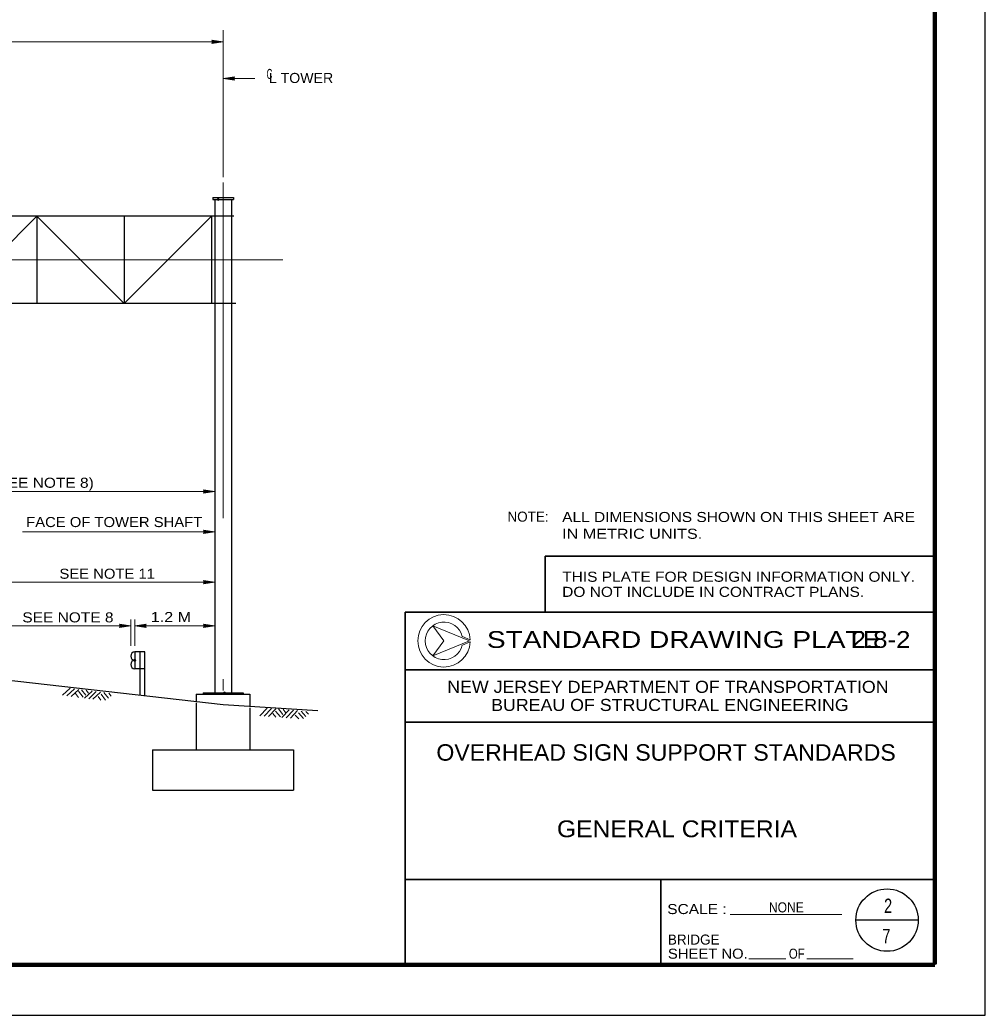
# Model space of a CAD drawing. Extents: x 312601.858 to 312602.699, y 144420.127 to 144420.721.
# Drawn here: x 312602.4113 to 312602.6988, y 144420.1268 to 144420.4233 of the extents above; entities that cross this region are included whole.
import ezdxf
from ezdxf.enums import TextEntityAlignment as Align

# ---------------------------------------------------------------- set-up
doc = ezdxf.new("R2010")
doc.units = 0
doc.header["$LTSCALE"] = 0.0012
doc.header["$PDMODE"] = 32
doc.header["$PDSIZE"] = 0.0006
doc.linetypes.add('DOT_DASHED', pattern=[7.7, 5, -1.2, 0.3, -1.2])
doc.linetypes.add('LONG_DASHED', pattern=[7.5, 6, -1.5])
for name, color, linetype, lineweight in [('1', 7, 'Continuous', 13), ('2', 7, 'Continuous', 13), ('39', 7, 'Continuous', 13)]:
    doc.layers.add(name, color=color, linetype=linetype, lineweight=lineweight)
doc.layers.add('4', color=7, linetype='Continuous')
doc.layers.add('51', color=7, linetype='Continuous')

msp = doc.modelspace()

# ---------------------------------------------------------------- hatches: boundary and pattern name
at = {"layer": '39'}
for points in [[(312602.4687, 144420.4168), (312602.4684, 144420.4173), (312602.4718, 144420.4168), (312602.4684, 144420.4163)], [(312602.4687, 144420.4168), (312602.4684, 144420.4173), (312602.4718, 144420.4168), (312602.4684, 144420.4163)], [(312602.4749, 144420.4058), (312602.4752, 144420.4053), (312602.4718, 144420.4058), (312602.4752, 144420.4063)], [(312602.4662, 144420.2828), (312602.4659, 144420.2833), (312602.4693, 144420.2828), (312602.4659, 144420.2823)], [(312602.4662, 144420.2828), (312602.4659, 144420.2833), (312602.4693, 144420.2828), (312602.4659, 144420.2823)], [(312602.4662, 144420.2708), (312602.4659, 144420.2713), (312602.4693, 144420.2708), (312602.4659, 144420.2703)], [(312602.4662, 144420.2708), (312602.4659, 144420.2713), (312602.4693, 144420.2708), (312602.4659, 144420.2703)], [(312602.4662, 144420.2558), (312602.4659, 144420.2563), (312602.4693, 144420.2558), (312602.4659, 144420.2553)], [(312602.4412, 144420.2428), (312602.4409, 144420.2433), (312602.4443, 144420.2428), (312602.4409, 144420.2423)], [(312602.4486, 144420.2428), (312602.4489, 144420.2423), (312602.4455, 144420.2428), (312602.4489, 144420.2433)], [(312602.4662, 144420.2428), (312602.4659, 144420.2433), (312602.4693, 144420.2428), (312602.4659, 144420.2423)], [(312602.4662, 144420.2428), (312602.4659, 144420.2433), (312602.4693, 144420.2428), (312602.4659, 144420.2423)], [(312602.4662, 144420.2428), (312602.4659, 144420.2433), (312602.4693, 144420.2428), (312602.4659, 144420.2423)]]:
    msp.add_hatch(color=256, dxfattribs=at).paths.add_polyline_path(points)

# ---------------------------------------------------------------- linework, layer by layer
at = {"layer": '1'}
for p, q in [((312602.5431, 144420.237), (312602.5454, 144420.238)), ((312602.4239, 144420.2221), (312602.4262, 144420.2242)), ((312602.4252, 144420.2219), (312602.4275, 144420.224)), ((312602.4265, 144420.2217), (312602.4288, 144420.2238)), ((312602.4278, 144420.2226), (312602.4287, 144420.2214)), ((312602.4287, 144420.2233), (312602.4301, 144420.2215)), ((312602.4296, 144420.2237), (312602.4309, 144420.2221)), ((312602.4305, 144420.2212), (312602.4328, 144420.2233)), ((312602.431, 144420.2236), (312602.4317, 144420.2227)), ((312602.4318, 144420.221), (312602.434, 144420.2232)), ((312602.433, 144420.2209), (312602.4353, 144420.223)), ((312602.4355, 144420.2224), (312602.4368, 144420.2206)), ((312602.4363, 144420.2229), (312602.4376, 144420.2212)), ((312602.4377, 144420.2227), (312602.4384, 144420.2218)), ((312602.4346, 144420.2217), (312602.4354, 144420.2206)), ((312602.4827, 144420.216), (312602.4849, 144420.2182)), ((312602.484, 144420.2159), (312602.4862, 144420.2181)), ((312602.4853, 144420.2158), (312602.4875, 144420.218)), ((312602.4866, 144420.2167), (312602.4875, 144420.2156)), ((312602.4874, 144420.2174), (312602.4889, 144420.2157)), ((312602.4883, 144420.218), (312602.4896, 144420.2164)), ((312602.4893, 144420.2155), (312602.4915, 144420.2177)), ((312602.4897, 144420.2179), (312602.4904, 144420.217)), ((312602.4906, 144420.2154), (312602.4928, 144420.2176)), ((312602.4919, 144420.2153), (312602.494, 144420.2175)), ((312602.4942, 144420.2169), (312602.4957, 144420.2152)), ((312602.495, 144420.2174), (312602.4964, 144420.2158)), ((312602.4964, 144420.2173), (312602.4972, 144420.2165)), ((312602.4933, 144420.2162), (312602.4943, 144420.2151)), ((312602.6284, 144420.1436), (312602.6394, 144420.1436)), ((312602.6457, 144420.1436), (312602.6595, 144420.1436))]:
    msp.add_line(p, q, dxfattribs=at)
for points in [[(312602.5452, 144420.2383), (312602.5343, 144420.2428), (312602.5452, 144420.2383)], [(312602.5454, 144420.2386), (312602.5431, 144420.2396), (312602.543, 144420.2396)]]:
    msp.add_lwpolyline(points, dxfattribs=at)
for points in [[(312602.5452, 144420.2383), (312602.5343, 144420.2428), (312602.5375, 144420.2383), (312602.5343, 144420.2338)], [(312602.5375, 144420.2383), (312602.5343, 144420.2338), (312602.5452, 144420.2383), (312602.5343, 144420.2428)]]:
    msp.add_lwpolyline(points, close=True, dxfattribs=at)
for radius, start, end in [(0.0078026, 2.21392, 357.78608), (0.0056, 13.69411, 346.30589)]:
    msp.add_arc((312602.5376, 144420.2383), radius, start, end, dxfattribs=at)
at = {"layer": '39', "lineweight": 25}
for p, q in [((312602.6988, 144420.1268), (312602.6988, 144420.7208)), ((312602.4687, 144420.3704), (312602.4687, 144420.3698)), ((312602.4687, 144420.3698), (312602.4749, 144420.3698)), ((312602.475, 144420.3648), (312601.9956, 144420.3648)), ((312602.3903, 144420.3388), (312602.4163, 144420.3648)), ((312602.4163, 144420.3648), (312602.4163, 144420.3388)), ((312602.4423, 144420.3388), (312602.4163, 144420.3648)), ((312602.4423, 144420.3648), (312602.4423, 144420.3388)), ((312602.4423, 144420.3388), (312602.4683, 144420.3648)), ((312602.4683, 144420.3648), (312602.4683, 144420.3388)), ((312602.4756, 144420.3388), (312601.9952, 144420.3388)), ((312602.447, 144420.235), (312602.447, 144420.2221)), ((312602.4485, 144420.2219), (312602.4485, 144420.235)), ((312602.4485, 144420.23), (312602.4455, 144420.23)), ((312602.4638, 144420.2224), (312602.4798, 144420.2224)), ((312602.4638, 144420.2224), (312602.4638, 144420.2202)), ((312602.4658, 144420.2228), (312602.4778, 144420.2228)), ((312602.4658, 144420.2228), (312602.4658, 144420.2224)), ((312602.4778, 144420.2228), (312602.4778, 144420.2224)), ((312602.4798, 144420.2224), (312602.4798, 144420.2188)), ((312602.6789, 144420.1551), (312602.6603, 144420.1551)), ((312601.8578, 144420.1268), (312602.6988, 144420.1268))]:
    msp.add_line(p, q, dxfattribs=at)
at = {"layer": '39', "lineweight": 158}
for p, q in [((312602.6838, 144420.142), (312602.6838, 144420.6818)), ((312601.9088, 144420.1418), (312602.6838, 144420.1418))]:
    msp.add_line(p, q, dxfattribs=at)
at = {"layer": '39'}
for p, q in [((312602.4718, 144420.4202), (312602.4718, 144420.3764)), ((312602.4718, 144420.4168), (312601.9448, 144420.4168)), ((312602.4812, 144420.4058), (312602.4718, 144420.4058)), ((312602.3095, 144420.2828), (312602.4693, 144420.2828)), ((312602.412, 144420.2708), (312602.4693, 144420.2708)), ((312602.4443, 144420.2447), (312602.4443, 144420.2368)), ((312602.4455, 144420.2447), (312602.4455, 144420.2368)), ((312602.4063, 144420.2428), (312602.4442, 144420.2428)), ((312602.4455, 144420.2428), (312602.4693, 144420.2428)), ((312602.4718, 144420.2269), (312602.4718, 144420.2235)), ((312602.6022, 144420.1672), (312602.6838, 144420.1672)), ((312602.6229, 144420.1568), (312602.6561, 144420.1568))]:
    msp.add_line(p, q, dxfattribs=at)
at = {"layer": '39', "linetype": 'DOT_DASHED'}
for p, q in [((312602.4718, 144420.3749), (312602.4718, 144420.2269)), ((312602.0009, 144420.3518), (312602.4896, 144420.3518))]:
    msp.add_line(p, q, dxfattribs=at)
at = {"layer": '39', "lineweight": 35}
for p, q in [((312602.5677, 144420.2635), (312602.6838, 144420.2635)), ((312602.5677, 144420.2468), (312602.5677, 144420.2635)), ((312602.526, 144420.1418), (312602.526, 144420.2468)), ((312602.526, 144420.2297), (312602.6838, 144420.2297)), ((312602.526, 144420.2141), (312602.6838, 144420.2141)), ((312602.526, 144420.1672), (312602.6838, 144420.1672)), ((312602.6022, 144420.1421), (312602.6022, 144420.1672))]:
    msp.add_line(p, q, dxfattribs=at)
at = {"layer": '39', "linetype": 'LONG_DASHED', "lineweight": 25}
for p, q in [((312602.4638, 144420.2198), (312602.4638, 144420.2058)), ((312602.4798, 144420.2183), (312602.4798, 144420.2058)), ((312602.4508, 144420.2058), (312602.4928, 144420.2058)), ((312602.4928, 144420.2058), (312602.4928, 144420.1938))]:
    msp.add_line(p, q, dxfattribs=at)
at = {"layer": '39'}
for points in [[(312602.4687, 144420.4168), (312602.4684, 144420.4173), (312602.4718, 144420.4168), (312602.4684, 144420.4163)], [(312602.4687, 144420.4168), (312602.4684, 144420.4173), (312602.4718, 144420.4168), (312602.4684, 144420.4163)], [(312602.4749, 144420.4058), (312602.4752, 144420.4053), (312602.4718, 144420.4058), (312602.4752, 144420.4063)], [(312602.4662, 144420.2828), (312602.4659, 144420.2833), (312602.4693, 144420.2828), (312602.4659, 144420.2823)], [(312602.4662, 144420.2828), (312602.4659, 144420.2833), (312602.4693, 144420.2828), (312602.4659, 144420.2823)], [(312602.4662, 144420.2708), (312602.4659, 144420.2713), (312602.4693, 144420.2708), (312602.4659, 144420.2703)], [(312602.4662, 144420.2708), (312602.4659, 144420.2713), (312602.4693, 144420.2708), (312602.4659, 144420.2703)], [(312602.4662, 144420.2558), (312602.4659, 144420.2563), (312602.4693, 144420.2558), (312602.4659, 144420.2553)], [(312602.4412, 144420.2428), (312602.4409, 144420.2433), (312602.4443, 144420.2428), (312602.4409, 144420.2423)], [(312602.4486, 144420.2428), (312602.4489, 144420.2423), (312602.4455, 144420.2428), (312602.4489, 144420.2433)], [(312602.4662, 144420.2428), (312602.4659, 144420.2433), (312602.4693, 144420.2428), (312602.4659, 144420.2423)], [(312602.4662, 144420.2428), (312602.4659, 144420.2433), (312602.4693, 144420.2428), (312602.4659, 144420.2423)], [(312602.4662, 144420.2428), (312602.4659, 144420.2433), (312602.4693, 144420.2428), (312602.4659, 144420.2423)], [(312602.5452, 144420.2383), (312602.5343, 144420.2428), (312602.5375, 144420.2383), (312602.5343, 144420.2338)]]:
    msp.add_lwpolyline(points, close=True, dxfattribs=at)
at = {"layer": '39', "lineweight": 25}
for points in [[(312602.4687, 144420.3704), (312602.4749, 144420.3704), (312602.4749, 144420.3698)], [(312602.4693, 144420.3698), (312602.4693, 144420.2263), (312602.4693, 144420.2228)], [(312602.4743, 144420.3698), (312602.4743, 144420.2262), (312602.4743, 144420.2228)], [(312602.4485, 144420.235), (312602.4455, 144420.235), (312602.4455, 144420.23)], [(312602.4063, 144420.2268), (312602.4718, 144420.2193), (312602.5, 144420.2175)]]:
    msp.add_lwpolyline(points, dxfattribs=at)
at = {"layer": '39'}
msp.add_lwpolyline([(312602.3095, 144420.2558), (312602.4063, 144420.2558), (312602.4693, 144420.2558)], dxfattribs=at)
at = {"layer": '39', "lineweight": 35}
msp.add_lwpolyline([(312602.526, 144420.2468), (312602.6838, 144420.2468), (312602.6838, 144420.1418)], dxfattribs=at)
at = {"layer": '39', "linetype": 'LONG_DASHED', "lineweight": 25}
msp.add_lwpolyline([(312602.4508, 144420.2058), (312602.4508, 144420.1938), (312602.4928, 144420.1938)], dxfattribs=at)
at = {"layer": '39', "lineweight": 25}
msp.add_circle((312602.6696, 144420.1551), 0.0093005, dxfattribs=at)
for centre in [(312602.4455, 144420.23375), (312602.4455, 144420.23125)]:
    msp.add_arc(centre, 0.00125, 90, 270, dxfattribs=at)
at = {"layer": '39'}
for p in [(312602.4703, 144420.3698), (312602.4455, 144420.2325), (312602.4722, 144420.2228)]:
    msp.add_point(p, dxfattribs=at)

# ---------------------------------------------------------------- texts
at = {"layer": '1', "width": 0.9}
msp.add_text('NONE', height=0.003, dxfattribs=at).set_placement((312602.6396, 144420.1574), align=Align.CENTER)
at = {"layer": '2'}
for s, height, width, p in [('C', 0.003, 0.6, (312602.4856, 144420.4057)), ('L TOWER', 0.003, 1.05, (312602.495, 144420.4045)), ('1.2 M', 0.003, 1.2, (312602.45625, 144420.2439)), ('2.8-2', 0.005, 1.15, (312602.6678, 144420.2362)), ('OVERHEAD SIGN SUPPORT STANDARDS', 0.0049, 1.05, (312602.60375, 144420.2026))]:
    msp.add_text(s, height=height, dxfattribs=dict(at, width=width)).set_placement(p, align=Align.CENTER)
at = {"layer": '2', "width": 1.15}
for s, p in [('THIS PLATE FOR DESIGN INFORMATION ONLY.', (312602.5728, 144420.2559)), ('DO NOT INCLUDE IN CONTRACT PLANS.', (312602.5728, 144420.2514))]:
    msp.add_text(s, height=0.003, dxfattribs=at).set_placement(p)
at = {"layer": '39'}
for s, height, width, p in [('DESIRABLE CLEAR ZONE (SEE NOTE 8) ', 0.003, 1.15, (312602.3898, 144420.2839)), ('FACE OF TOWER SHAFT', 0.003, 1.1, (312602.43935, 144420.2722)), ('SEE NOTE 11', 0.003, 1.1, (312602.43725, 144420.2568)), ('SEE NOTE 8', 0.003, 1.15, (312602.42555, 144420.2438)), ('STANDARD DRAWING PLATE       ', 0.005, 1.25, (312602.61725, 144420.2362)), ('NEW JERSEY DEPARTMENT OF TRANSPORTATION', 0.003599, 1.1, (312602.6043, 144420.2228)), ('BUREAU OF STRUCTURAL ENGINEERING', 0.0036, 1.1, (312602.6049, 144420.2174)), ('GENERAL CRITERIA', 0.005, 1.1, (312602.607, 144420.1798)), ('SCALE :', 0.003, 1.15, (312602.61295, 144420.1569)), ('OF', 0.003, 0.85, (312602.6427, 144420.1436))]:
    msp.add_text(s, height=height, dxfattribs=dict(at, width=width)).set_placement(p, align=Align.CENTER)
msp.add_text('BRIDGE', height=0.003, dxfattribs=at).set_placement((312602.6043, 144420.1478))
at = {"layer": '39', "width": 1.1}
msp.add_text('SHEET NO.', height=0.003, dxfattribs=at).set_placement((312602.6043, 144420.1436))
at = {"layer": '4'}
msp.add_text('NOTE:', height=0.003, dxfattribs=at).set_placement((312602.5565, 144420.2738))
for s, width, p in [('ALL DIMENSIONS SHOWN ON THIS SHEET ARE', 1.15, (312602.5728, 144420.2737)), ('IN METRIC UNITS.', 1.2, (312602.5728, 144420.2687))]:
    msp.add_text(s, height=0.003, dxfattribs=dict(at, width=width)).set_placement(p)
at = {"layer": '51', "width": 0.75}
for s, p in [('2', (312602.6699, 144420.1572)), ('7', (312602.6694, 144420.1482))]:
    msp.add_text(s, height=0.0043, dxfattribs=at).set_placement(p, align=Align.CENTER)

doc.saveas('drawing.dxf')
